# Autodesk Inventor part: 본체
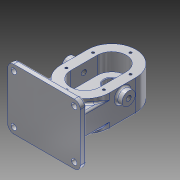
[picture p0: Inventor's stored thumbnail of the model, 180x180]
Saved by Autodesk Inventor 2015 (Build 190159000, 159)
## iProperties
Created: 2020-09
Part Number: 본체
Material: 알루미늄 6061
Document SubType Name: Modeling
Designer: Administrator
Density: 2.7 g/cm^3
Appearance: 알루미늄 - 평지
Mass: 1440.46 g
Surface Area: 785.636 cm^2
Volume: 533.505 cm^3
Author: Administrator
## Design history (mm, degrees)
sketch "스케치1"
  geometry: L1 (0, 0)-(0, 44); L2 (0, 0)-(0, 44); L3 (40, 0)-(40, 44); L4 (-40, 44)-(-40, 0); A1 r 40 centre (0, 0) between (-40, 0) and (40, 0); A2 r 40 centre (0, 44) between (40, 44) and (-40, 44); 1 further point
  constraints: 10 end point, 4 point on circle, 4 tangent, 2 centre point, 2 vertical, 1 midpoint, 1 parallel
  dimensions: "d0" = 44 distance of L1.start L1.end; "d1" = 40 radius of A2
extrude "돌출1" new body sketch "스케치1" distance "d2" = 53; taper "d3" = 0 deg
sketch "스케치2"
  geometry: L1 (0, 0)-(0, 44); L2 (24, 0)-(24, 44); L3 (-24, 44)-(-24, 0); A1 r 24 centre (0, 0) between (-24, 0) and (24, 0); A2 r 24 centre (0, 44) between (24, 44) and (-24, 44); 1 further point
  constraints: 8 end point, 4 point on circle, 4 tangent, 2 centre point, 1 midpoint, 1 parallel, 1 vertical
  dimensions: "d4" = 44 distance of L1.start L1.end; "d5" = 24 radius of A2
extrude "돌출2" cut sketch "스케치2" distance "d6" = 29; taper "d7" = 0 deg
sketch "스케치3"
  geometry: L1 (0, 0)-(0, 44); C1 r 12.5 at (0, 44); C2 r 12.5 at (0, 0); 1 further point
  constraints: 3 coincident, 2 centre point, 2 end point, 1 vertical
  dimensions: "d9" = 44 distance of L1.start L1.end; "d10" = 25 diameter of C1; "d11" = 25 diameter of C2
extrude "돌출3" cut sketch "스케치3" distance "d12" = 15; taper "d13" = 0 deg
sketch "스케치4"
  geometry: C1 r 12.5 at (0, 0) reference; C2 r 8.5 at (0, 0); 1 further point
  constraints: 1 centre point, 1 coincident
  dimensions: "d14" = 17 diameter of C2
extrude "돌출4" cut sketch "스케치4" stored distance "d15" = 15; taper "d16" = 0 deg
sketch "스케치5"
  geometry: C1 r 8.5 at (0, 44) reference; C2 r 19 at (0, 44); 1 further point
  constraints: 1 centre point, 1 coincident
  dimensions: "d17" = 38 diameter of C2
extrude "돌출5" join sketch "스케치5" distance "d18" = 17; taper "d19" = 0 deg
sketch "스케치6"
  geometry: C1 r 19 at (0, 0) reference; C2 r 14 at (0, 0); 1 further point
  constraints: 1 centre point, 1 coincident
  dimensions: "d20" = 28 diameter of C2
extrude "돌출6" cut sketch "스케치6" distance "d21" = 7.3; taper "d22" = 0 deg
sketch "스케치7"
  geometry: L1 (0, 0)-(0, 44); L2 (0, 0)-(0, 44); L3 (31, 0)-(31, 44); L4 (-31, 44)-(-31, 0); L5 (0, 22)-(31, 22); L6 (31, 22)-(31, 44); L7 (31, 22)-(31, 0); L8 (0, 22)-(-31, 22); L9 (-31, 22)-(-31, 44); L10 (-31, 22)-(-31, 0); L11 (0, 22)-(0, 75); L12 (0, 22)-(0, -31); A1 r 31 centre (0, 0) between (-31, 0) and (31, 0); A2 r 31 centre (0, 44) between (31, 44) and (-31, 44)
  constraints: 26 end point, 6 point on circle, 5 tangent, 3 equal length, 3 midpoint, 2 centre point, 2 perpendicular, 2 vertical
  dimensions: "d23" = 44 distance of L1.start L1.end; "d24" = 62 diameter of A2
hole "구멍1" sketch "스케치7" at (0, 75), (-31, 44), (-31, 0), (31, 0), (31, 44), (0, -31) diameter "d25" = 4.134; stored, may be unused: countersink angle "d29" = 82 deg, drill point angle "d31" = 118 deg; dims "d26" = 10, "d27" = 3.023, "d28" = 2, "d30" = 12
node "작업 평면1"
sketch "스케치8"
  geometry: L1 (-19, -17)-(19, -17) reference; L2 (19, 0)-(19, -17) reference; L3 (0, -17)-(60, -17); L4 (60, -17)-(60, 83); L5 (60, 83)-(-60, 83); L6 (-60, 83)-(-60, -17); L7 (-60, -17)-(0, -17); 1 further point
  constraints: 10 end point, 2 perpendicular, 1 collinear, 1 horizontal, 1 midpoint, 1 point on line
  dimensions: "d33" = 60 distance of L3.start L3.end; "d34" = 100 distance of L3.end L4.end; "d35" = 120 distance of L4.end L5.end; "d36" = 100 distance of L5.end L6.end
extrude "돌출7" join sketch "스케치8" distance "d37" = 10; taper "d38" = 0 deg
node "작업 평면2"
sketch "스케치9"
  geometry: L1 (-60, -68)-(-60, -58) reference; L2 (60, -68)-(60, -58) reference; L3 (-60, -58)-(60, -58) reference; L4 (0, -58)-(-40, -58); L5 (-40, -58)-(-40, 0); L6 (0, -58)-(40, -58); L7 (40, -58)-(40, 0); A1 r 40 centre (0, 0) between (-40, 0) and (40, 0) reference; A2 r 40 centre (0, 0) between (-40, 0) and (40, 0); 1 further point
  constraints: 8 end point, 2 point on circle, 2 point on line, 1 centre point, 1 concentric, 1 midpoint
  dimensions: "d40" = 40 distance of L4.start L4.end; "d41" = 40 distance of L4.start L6.end
extrude "돌출8" join sketch "스케치9" stored distance "d42" = 37; taper "d43" = 0 deg
fillet "모깎기1" dims "d44" = 10
sketch "스케치13"
  geometry: C1 r 4.5 at (-50, -73); C2 r 4.5 at (-50, 7); C3 r 4.5 at (50, 7); C4 r 4.5 at (50, -73); A1 r 10 centre (-50, -73) between (-60, -73) and (-50, -83) reference; A2 r 10 centre (-50, 7) between (-50, 17) and (-60, 7) reference; A3 r 10 centre (50, 7) between (60, 7) and (50, 17) reference; A4 r 10 centre (50, -73) between (50, -83) and (60, -73) reference; 1 further point
  constraints: 4 centre point, 4 coincident
  dimensions: "d51" = 9 diameter of C1; "d52" = 9 diameter of C2; "d53" = 9 diameter of C3; "d54" = 9 diameter of C4
extrude "돌출10" cut sketch "스케치13" stored distance "d55" = 37; taper "d56" = 0 deg
sketch "스케치14"
  geometry: L1 (-73, -68)-(7, -68) reference; L2 (-53, 0)-(-53, 44) reference; L3 (0, 0)-(0, 44) reference; L4 (-53, 22)-(-39, 22); C1 r 11 at (-39, 22)
  constraints: 2 end point, 1 centre point, 1 coincident, 1 horizontal, 1 midpoint
  dimensions: "d57" = 14 distance of L4.start L4.end; "d58" = 22 diameter of C1
extrude "돌출11" join sketch "스케치14" distance "d59" = 10; taper "d60" = 0 deg
fillet "모깎기2" dims "d71" = 3
fillet "모깎기3" dims "d72" = 3
chamfer "모따기1" distance "d73" = 0.7; stored, may be unused: second distance "d74" = 2, angle "d75" = 30 deg
fillet "모깎기4" dims "d76" = 0.5
chamfer "모따기2" distance "d77" = 1; stored, may be unused: second distance "d78" = 2, angle "d79" = 30 deg
sketch "스케치19"
  geometry: C1 r 11 at (39, 22) reference; C2 r 11 at (39, 22); 1 further point
  constraints: 1 centre point, 1 coincident
  dimensions: "d80" = 22 diameter of C2
extrude "돌출13" join sketch "스케치19" distance "d81" = 10; taper "d82" = 0 deg
sketch "스케치20"
  geometry: C1 r 11 at (0, 0) reference; 1 further point
hole "구멍3" sketch "스케치20" at (0, 0) diameter "d83" = 8.376; stored, may be unused: countersink angle "d87" = 82 deg, drill point angle "d89" = 118 deg; dims "d84" = 27, "d85" = 3.023, "d86" = 2, "d88" = 34.3
sketch "스케치21"
  geometry: C1 r 11 at (0, 0) reference; 1 further point
hole "구멍4" sketch "스케치21" at (0, 0) diameter "d90" = 8.376; stored, may be unused: countersink angle "d94" = 82 deg, drill point angle "d96" = 118 deg; dims "d91" = 27, "d92" = 3.023, "d93" = 2, "d95" = 34.3
fillet "모깎기5" dims "d97" = 3
sketch "스케치22"
  geometry: L1 (-60, 7)-(-60, -73) reference; L2 (-50, -83)-(50, -83) reference; 2 further points
  constraints: 1 other
  dimensions: "d98" = 60 distance from line of point (0, -71) L1; "d99" = 12 distance from line of point (0, -71) L2
feature "엠보싱1" sketch "스케치22" dims "d9" = 44, "d10" = 25, "d11" = 25, "d100" = 0.5, "d101" = 0
fillet "모깎기6" dims "d102" = 3
node "솔리드1"
node "투영된 루프3"
other parameters: "d32" = -68, "d39" = 26.5
